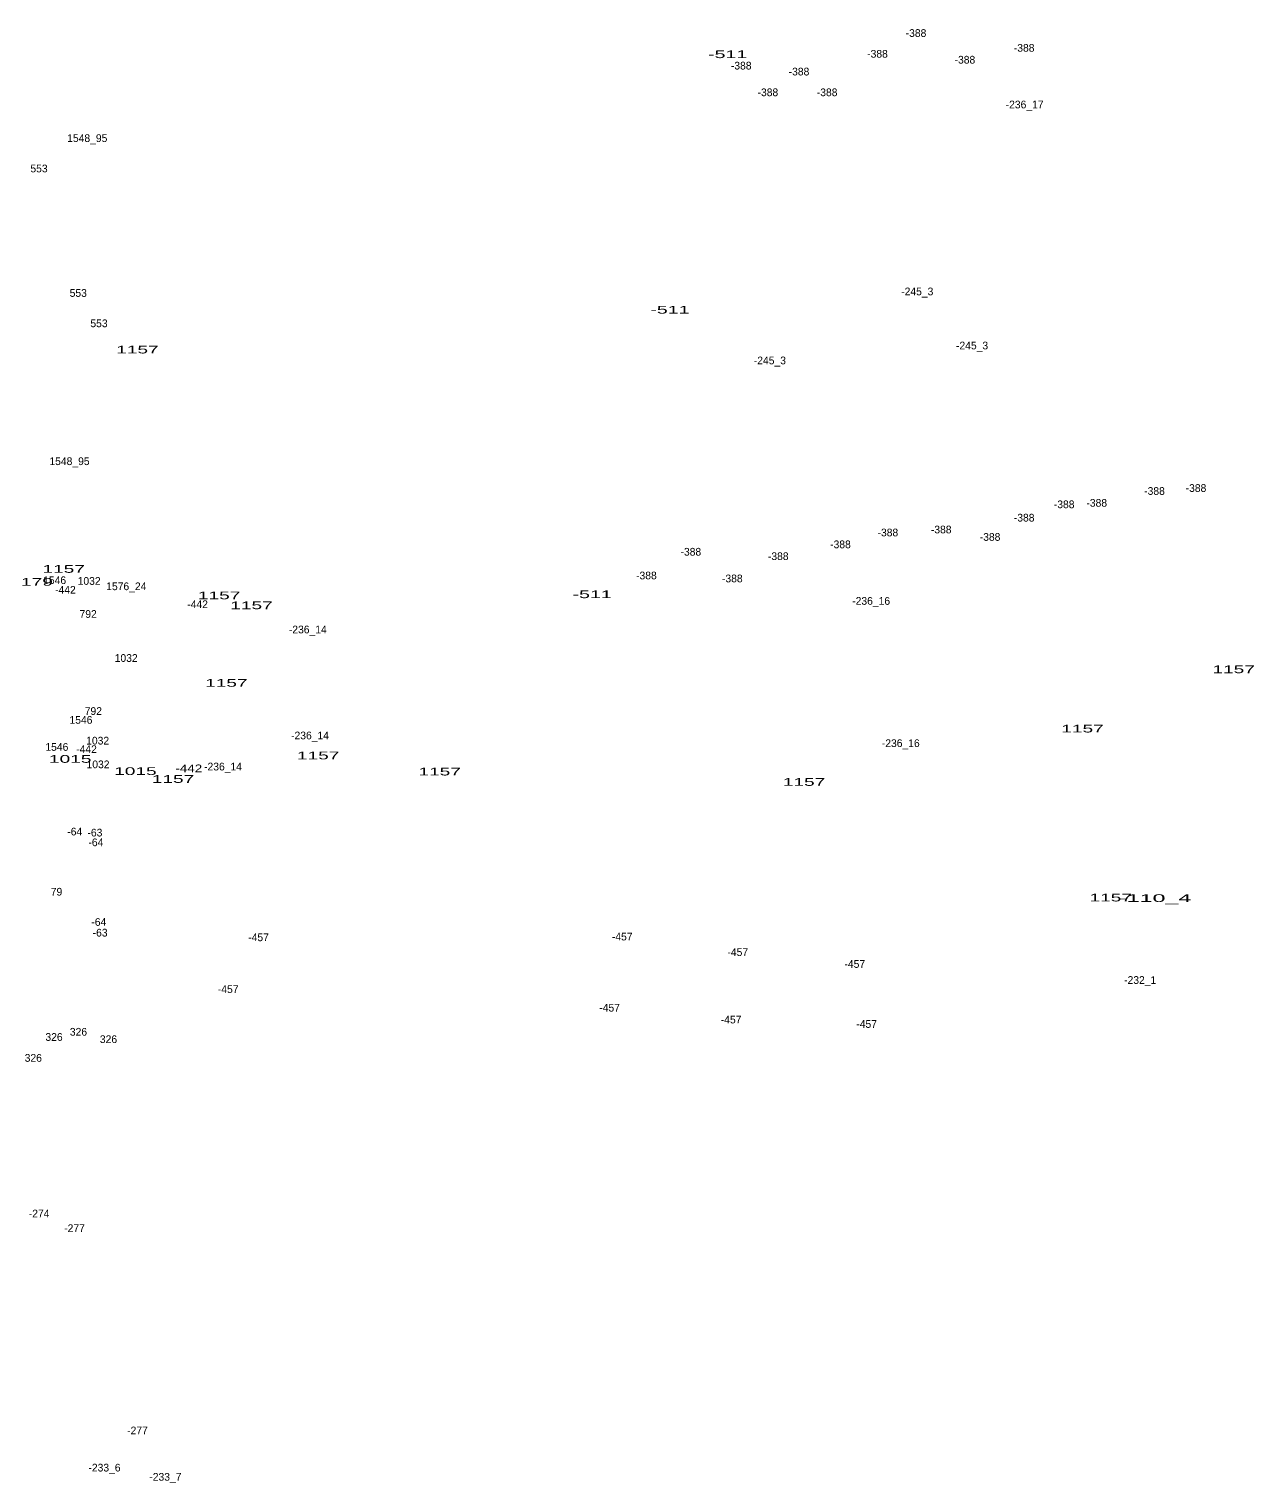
# Model space of a CAD drawing. Extents: x -660434 to -656144, y -997850 to -994016.
# Drawn here: x -657690 to -657055, y -997006 to -996252 of the extents above; entities that cross this region are included whole.
import ezdxf
from ezdxf.enums import TextEntityAlignment as Align

# ---------------------------------------------------------------- set-up
doc = ezdxf.new("R2010")
doc.units = 0
doc.header["$LTSCALE"] = 1.6
doc.layers.add('24', color=7, linetype='Continuous')

msp = doc.modelspace()

# ---------------------------------------------------------------- texts
at = {"layer": '24'}
for s, p in [('-388', (-657229.985, -996256.44)), ('-388', (-657249.955, -996267.2)), ('-388', (-657173.915, -996264.12)), ('-388', (-657320.615, -996273.34)), ('-388', (-657204.635, -996270.27)), ('-388', (-657290.655, -996276.42)), ('-388', (-657306.785, -996287.17)), ('-388', (-657276.065, -996287.17)), ('-236_17', (-657173.676, -996293.48)), ('1548_95', (-657659.657, -996310.92)), ('553', (-657684.677, -996326.65)), ('553', (-657664.327, -996391.18)), ('-245_3', (-657229.327, -996390.39)), ('553', (-657653.577, -996406.93)), ('-245_3', (-657200.917, -996418.43)), ('-245_3', (-657305.747, -996426.16)), ('1548_95', (-657668.877, -996478.41)), ('-388', (-657106.335, -996493.85)), ('-388', (-657084.825, -996492.31)), ('-388', (-657153.175, -996500.76)), ('-388', (-657136.285, -996500)), ('-388', (-657173.915, -996507.68)), ('-388', (-657244.575, -996515.36)), ('-388', (-657216.925, -996513.82)), ('-388', (-657269.155, -996521.51)), ('-388', (-657191.585, -996517.67)), ('-388', (-657346.725, -996525.35)), ('-388', (-657301.405, -996527.65)), ('-388', (-657369.765, -996537.64)), ('-388', (-657325.225, -996539.18)), ('1546', (-657676.58, -996540.1)), ('-442', (-657670.993, -996545.07)), ('1032', (-657658.694, -996540.48)), ('1576_24', (-657639.423, -996543.25)), ('-442', (-657602.453, -996552.56)), ('-236_16', (-657253.246, -996550.83)), ('792', (-657659.208, -996557.6)), ('-236_14', (-657545.315, -996565.64)), ('1032', (-657639.484, -996580.43)), ('1546', (-657662.94, -996612.51)), ('792', (-657656.518, -996607.93)), ('-236_14', (-657544.165, -996620.58)), ('1546', (-657675.42, -996626.53)), ('-442', (-657660.043, -996627.66)), ('1032', (-657654.274, -996623.27)), ('-236_16', (-657237.886, -996624.58)), ('1032', (-657654.084, -996635.56)), ('-236_14', (-657589.285, -996636.71)), ('-64', (-657666.155, -996670.41)), ('-63', (-657655.69, -996670.95)), ('-64', (-657655.205, -996675.98)), ('79', (-657675.608, -996701.61)), ('-64', (-657653.675, -996717.27)), ('-63', (-657653, -996722.82)), ('-457', (-657570.855, -996725.22)), ('-457', (-657382.305, -996724.84)), ('-457', (-657322.395, -996732.9)), ('-457', (-657261.725, -996739.05)), ('-232_1', (-657113.766, -996747.37)), ('-457', (-657586.605, -996752.11)), ('-457', (-657388.835, -996761.72)), ('-457', (-657325.855, -996767.86)), ('-457', (-657255.585, -996770.17)), ('326', (-657676.893, -996776.89)), ('326', (-657664.223, -996774.2)), ('326', (-657648.663, -996778.04)), ('326', (-657687.643, -996787.74)), ('-274', (-657684.625, -996868.41)), ('-277', (-657666.275, -996876.01)), ('-277', (-657633.635, -996980.88)), ('-233_6', (-657650.728, -997000.15)), ('-233_7', (-657619.158, -997004.92))]:
    msp.add_text(s, height=4, dxfattribs=at).set_placement(p, align=Align.CENTER)
for s, width, p in [('-511', 1.9, (-657327.627, -996267.42)), ('-511', 1.9, (-657357.577, -996399.88)), ('1157', 1.85, (-657633.639, -996420.53)), ('1157', 1.85, (-657671.889, -996534.24)), ('1179', 1.85, (-657688.513, -996540.95)), ('1157', 1.85, (-657591.289, -996547.98)), ('1157', 1.85, (-657574.499, -996553.12)), ('-511', 1.9, (-657397.897, -996547.4)), ('1157', 1.85, (-657065.299, -996586.3)), ('1157', 1.85, (-657587.559, -996593.32)), ('1157', 1.85, (-657143.639, -996617.03)), ('1015', 1.85, (-657668.51, -996632.74)), ('1157', 1.85, (-657539.939, -996630.96)), ('1015', 1.85, (-657634.71, -996639.08)), ('1157', 1.85, (-657615.199, -996643.15)), ('-442', 1.3, (-657607.03, -996637.65)), ('1157', 1.85, (-657476.959, -996639.31)), ('1157', 1.85, (-657288.019, -996644.69)), ('1157', 1.85, (-657129.039, -996704.62)), ('-110_4', 2.25, (-657106.009, -996704.91))]:
    msp.add_text(s, height=4, dxfattribs=dict(at, width=width)).set_placement(p, align=Align.CENTER)

doc.saveas('drawing.dxf')
